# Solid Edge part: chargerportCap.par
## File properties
Author: morva
Template: iso metric part.par
Last saved by: morva
Revision: 6
Application: Solid Edge
Density: 1050.000 kg/m^3
Accuracy: 0.990
Username: morva
Material: Polyurethene
Face Style: Blue
Fill Style: ANSI34(Plastic)
Virtual Style: ANSI34(Plastic)
Grouping: Non-metals\Plastics
LibraryName: Materials
Coef. of Thermal Exp: 9e-05
Thermal Conductivity: 0.2
Specific Heat: 0.0
Modulus of Elasticity: 0.0
Poisson's Ratio: 0.4
Yield Stress: 0.0
Ultimate Stress: 0.0
Elongation: 0.0
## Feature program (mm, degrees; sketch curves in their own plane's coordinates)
sketch for "unnamed RevolvedProtrusion 1" plane through (0, 0, 0) normal (0, -1, 0) x-axis (1, 0, 0)
  line (-3.5, 7.5) -> (5.5, 8)
  line (5.5, 8) -> (5.5, 12.5)
  line (5.5, 12.5) -> (8.5, 12.5)
  line (8.5, 12.5) -> (8.5, 0)
  line (8.5, 0) -> (3.5, 0)
  line (3.5, 0) -> (3.5, 5)
  line (3.5, 5) -> (-3.5, 5)
  line (-3.5, 5) -> (-3.5, 7.5)
  dimension (linear) = 5.5
  dimension (linear) = 8.5
  dimension (linear) = 3.5
revolve "unnamed RevolvedProtrusion 1" add full turn 360 deg
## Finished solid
Body 1: solid body, 7 faces, 6 edges, 0 vertices.
  Faces by surface: plane 4, cylinder 2, cone 1
  Edges by curve: circle 6
Bounding box of the edges (mm): 12.000 x 25.000 x 25.000, from (-3.5, -12.5, -12.5) to (8.5, 12.5, 12.5).
Cylindrical faces by radius (mm): R5 x1, R12.5 x1
Conical faces (half-angle, radius in mm at the cone's reference point): 3.1798 deg R7.5 x1
Planar faces by outward normal: +x 1, -x 3
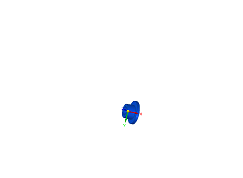
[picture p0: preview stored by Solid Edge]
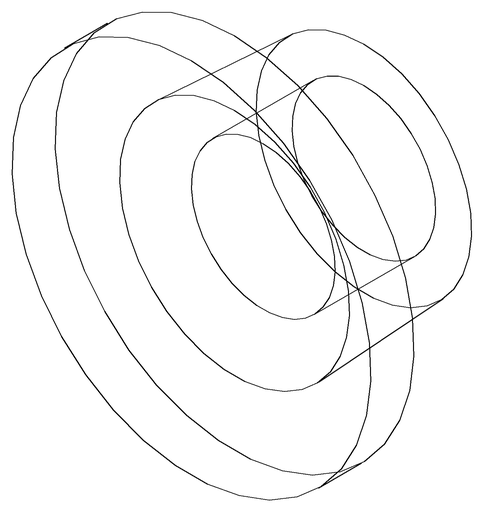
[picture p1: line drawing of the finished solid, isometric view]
